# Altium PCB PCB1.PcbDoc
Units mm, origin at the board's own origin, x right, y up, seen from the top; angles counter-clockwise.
Board outline 80 x 70 mm, 2 copper layers (Top Layer, Bottom Layer); 81 components, 50 nets, 233 pads, 0 vias.
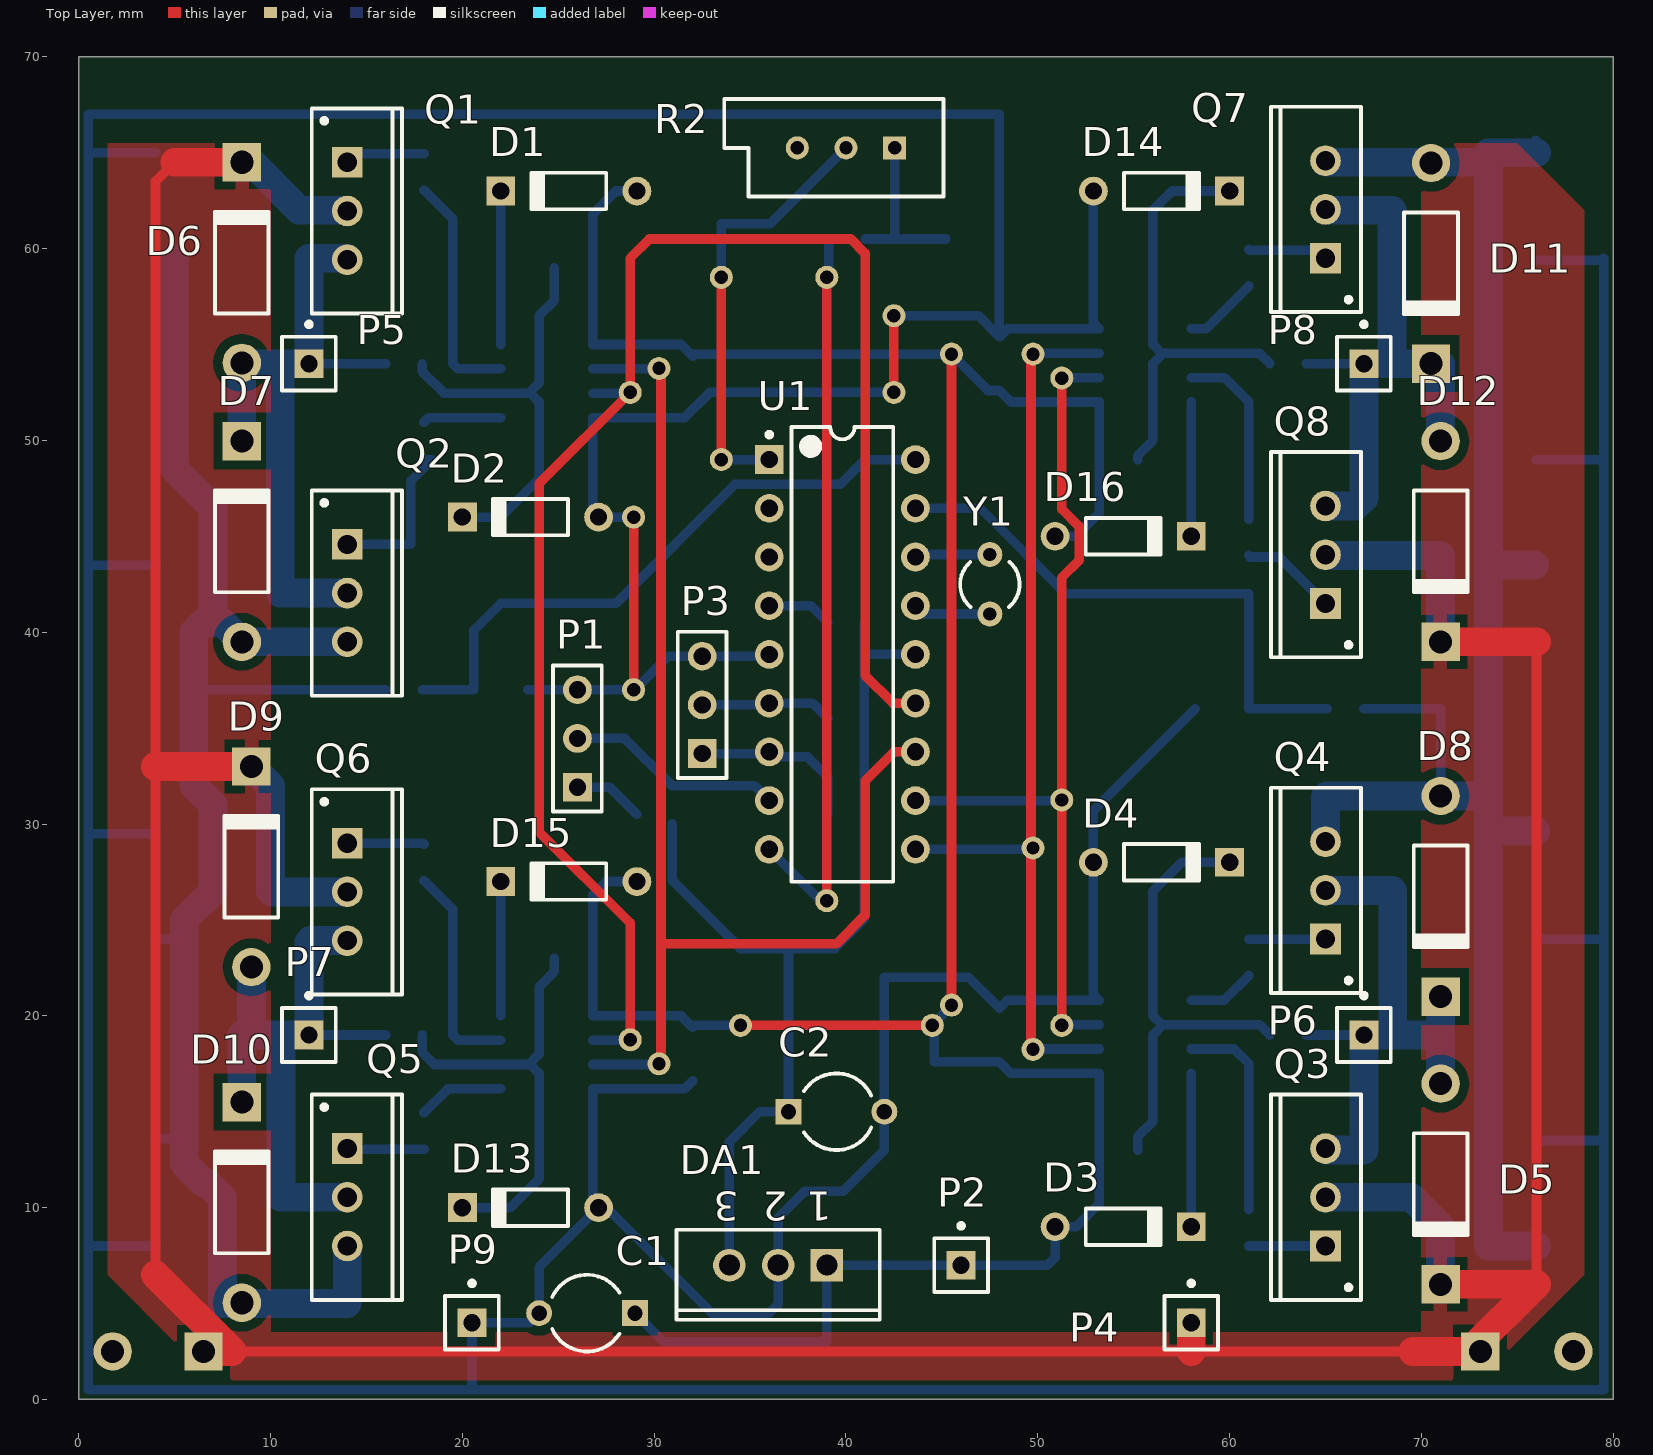
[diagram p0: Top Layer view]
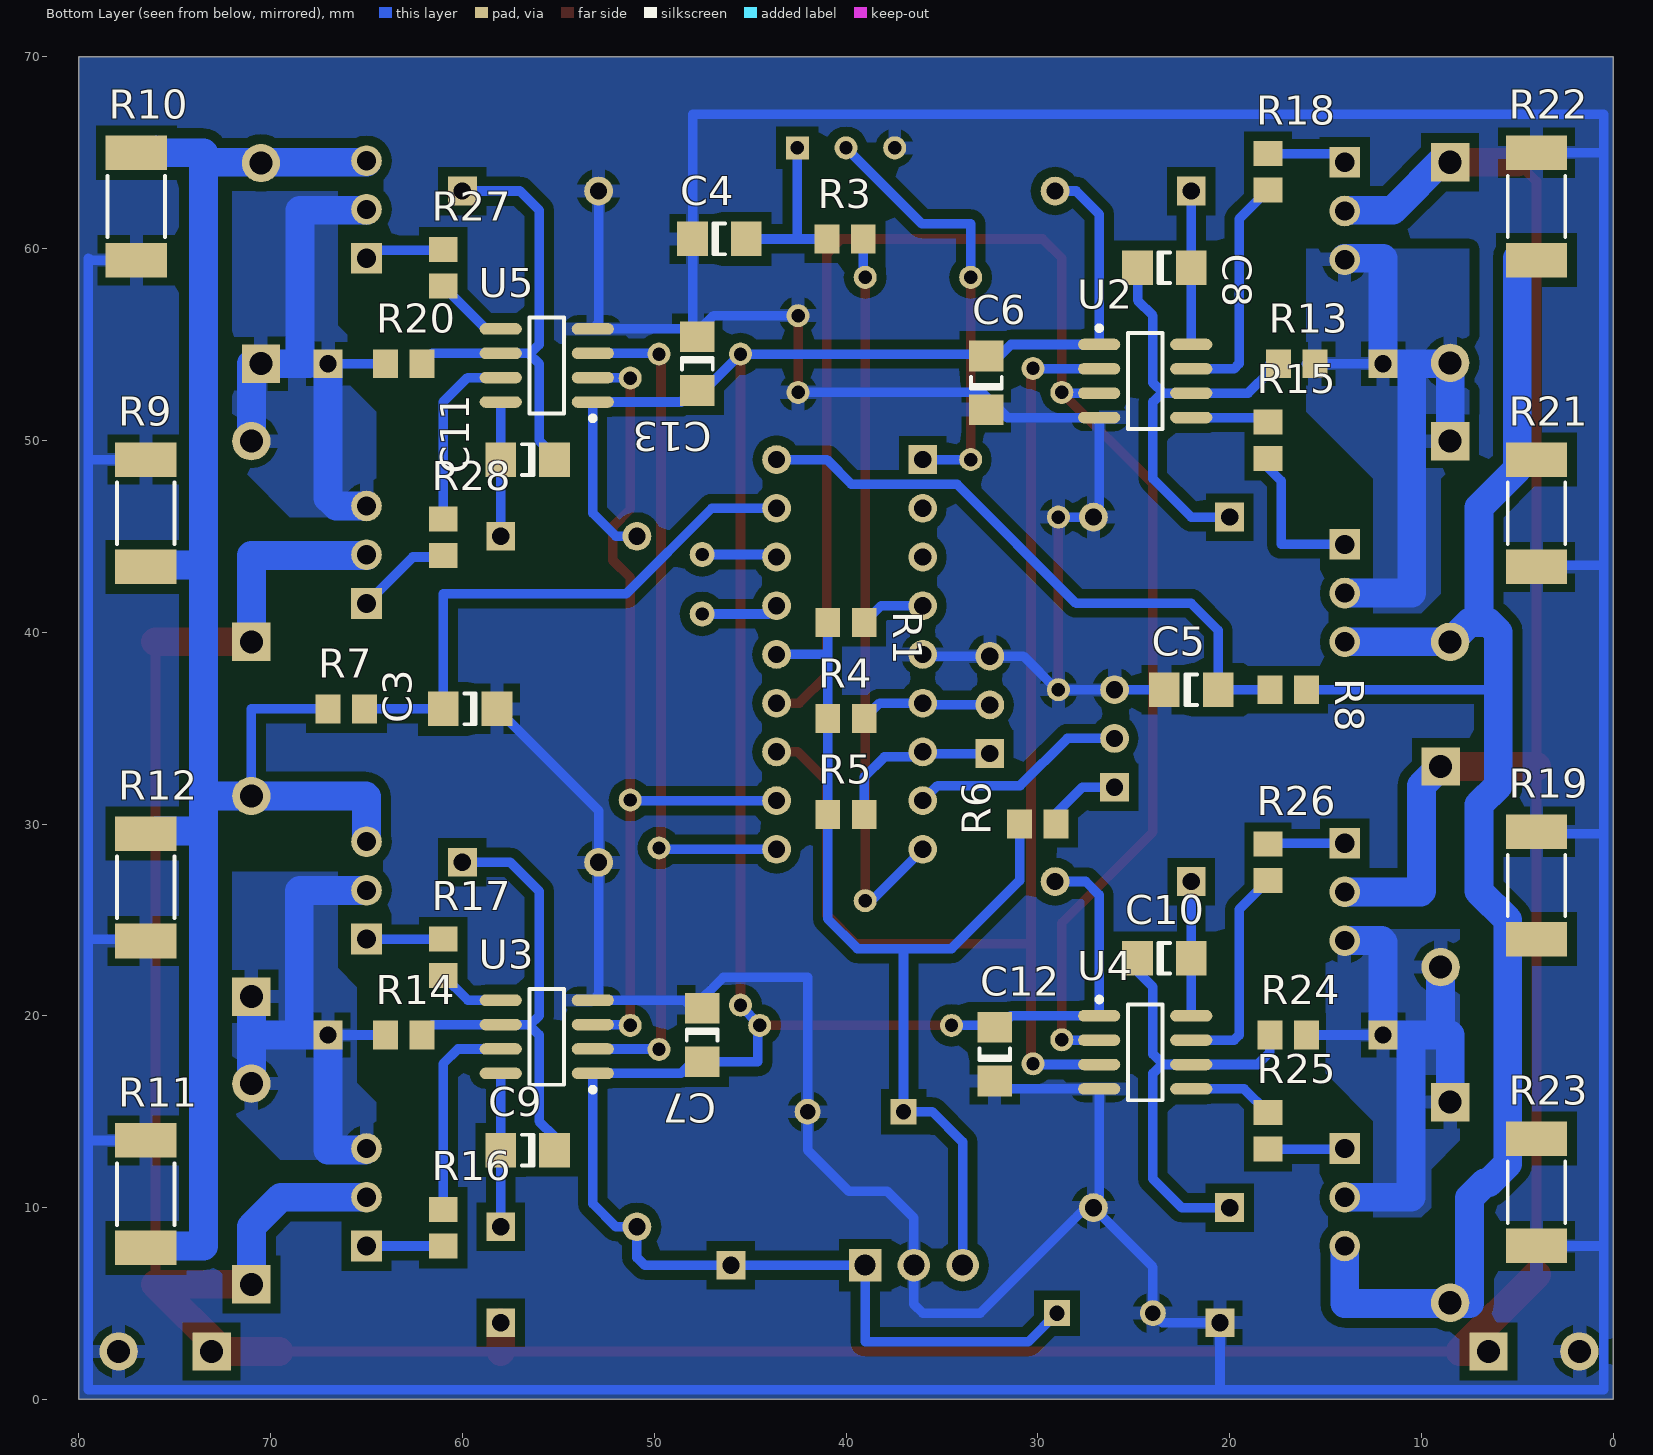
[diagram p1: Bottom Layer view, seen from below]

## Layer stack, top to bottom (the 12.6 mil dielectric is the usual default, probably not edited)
Top Solder: solder mask 0.0102, Solder Resist, Dk 3.5
Top Layer: signal copper 0.0356
Dielectric 1: dielectric 0.32, FR-4, Dk 4.8
Bottom Layer: signal copper 0.0356
Bottom Solder: solder mask 0.0102, Solder Resist, Dk 3.5

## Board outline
0,0 80,0 80,70 0,70

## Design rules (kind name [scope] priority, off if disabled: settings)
Clearance [InPolygon] p1: gap=0.5 ignorepadtopadclearanceinfootprint=FALSE
Clearance Clearance_1 [All] p2: gap=0.254 ignorepadtopadclearanceinfootprint=FALSE except(0: Arc-Hole Track-Hole SMDPad-Hole THPad-Hole Via-Hole Fill-Hole Poly-Hole Region-Hole Text-Hole)
PolygonConnect [All] p1: connectstyle=Relief reliefconductorwidth=0.7 reliefentries=4 polygonreliefangle="90 Angle" airgapwidth=0.4
RoomDefinition Sheet1 [InComponentClass('Sheet1')] p1: confinementstyle=ConfineOut formatcopy=TRUE lockcomponents=FALSE outline -17.25,-31.5 -12,-31.5 -12,-24.75 -17.25,-24.75
RoutingVias [All] p1: holewidth=0.711 width=1.27 viastyle="Through Hole" minholewidth=0.711 minwidth=1.27 maxholewidth=0.711 maxwidth=1.27
SolderMaskExpansion [All] p1: expansion=0.102
Width [All] p1: maxlimit=5 minlimit=0.5 preferedwidth=0.5
30 further rules are at their usual default settings.

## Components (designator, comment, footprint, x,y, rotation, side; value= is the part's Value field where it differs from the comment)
C1 "220x25" CAPR5-4X5 26.5,4.5 r180 top
C2 "10x15" CAPR5-4X5 39.5,15 r0 top
C3 "220pf" 1206 59.6,36 r0 bottom
C4 "100nf" 1206 46.6,60.5 r180 bottom
C5 "220pf" 1206 22,37 r180 bottom
C6 "100nf" 1206 32.682,53 r90 bottom
C7 "100nf" 1206 47.5,19 r270 bottom
C8 "470nf" 1206 23.4,59 r180 bottom
C9 "470nf" 1206 56.6,13 r0 bottom
C10 "470nf" 1206 23.4,23 r180 bottom
C11 "470nf" 1206 56.6,49 r0 bottom
C12 "100nf" 1206 32.247,18 r90 bottom
C13 "100nf" 1206 47.75,54 r270 bottom
D1 "1N4148" DO-35 25.55,63 r180 top
D2 "Diode 1N4148" DO-35 23.55,46 r180 top
D3 "1N4148" DO-35 54.45,9 r0 top
D4 "Diode 1N4148" DO-35 56.45,28 r0 top
D5 "FR307" DO-41 71,11.23 r270 top
D6 "FR307" DO-41 8.5,59.27 r90 top
D7 "FR307" DO-41 8.5,44.73 r90 top
D8 "FR307" DO-41 71,26.23 r270 top
D9 "FR307" DO-41 9,27.77 r90 top
D10 "FR307" DO-41 8.5,10.27 r90 top
D11 "FR307" DO-41 70.5,59.23 r270 top
D12 "FR307" DO-41 71,44.73 r270 top
D13 "Diode 1N4148" DO-35 23.55,10 r180 top
D14 "Diode 1N4148" DO-35 56.45,63 r0 top
D15 "1N4148" DO-35 25.55,27 r180 top
D16 "1N4148" DO-35 54.45,45 r0 top
DA1 "L78M05CV" TO-220A 36.46,7 r180 top
P1 "Header 3" HDR1X3 26,31.92 r90 top
P2 "A" PIN1 46,7 r0 top
P3 "Header 3" HDR1X3 32.5,33.67 r90 top
P4 "A" PIN1 58,4 r0 top
P5 "A" PIN1 12,54 r0 top
P6 "B" PIN1 67,19 r0 top
P7 "C" PIN1 12,19 r0 top
P8 "D" PIN1 67,54 r0 top
P9 "A" PIN1 20.5,4 r0 top
Q1 "IRFZ44" TO-220AB 14,61.96 r270 top
Q2 "IRFZ44" TO-220AB 14,42.04 r270 top
Q3 "IRFZ44" TO-220AB 65,10.54 r90 top
Q4 "IRFZ44" TO-220AB 65,26.54 r90 top
Q5 "IRFZ44" TO-220AB 14,10.54 r270 top
Q6 "IRFZ44" TO-220AB 14,26.46 r270 top
Q7 "IRFZ44" TO-220AB 65,62.04 r90 top
Q8 "IRFZ44" TO-220AB 65,44.04 r90 top
R1 "10k" 6-0805 40,40.5 r180 bottom
R2 "10k" VR5 40,65.25 r180 top value=1K
R3 "10k" 6-0805 40.05,60.5 r180 bottom
R4 "4.7k" 6-0805 40,35.5 r0 bottom
R5 "4.7k" 6-0805 40,30.5 r0 bottom
R6 "4.7k" 6-0805 30,30 r0 bottom
R7 "1k" 6-0805 66.05,36 r0 bottom
R8 "1k" 6-0805 16.95,37 r180 bottom
R9 "1om" 1T-2512 76.5,46.2 r270 bottom
R10 "1om" 1T-2512 77,62.2 r90 bottom
R11 "1om" 1T-2512 76.5,10.7 r270 bottom
R12 "1om" 1T-2512 76.5,26.7 r90 bottom
R13 "10om" 6-0805 16.498,54 r180 bottom
R14 "10om" 6-0805 63.05,19 r0 bottom
R15 "33om" 6-0805 18,50 r270 bottom
R16 "33om" 6-0805 61,8.95 r270 bottom
R17 "33om" 6-0805 61,23.05 r90 bottom
R18 "33om" 6-0805 18,64 r90 bottom
R19 "1om" 1T-2512 4,26.8 r90 bottom
R20 "10om" 6-0805 63.05,54 r180 bottom
R21 "1om" 1T-2512 4,46.2 r270 bottom
R22 "1om" 1T-2512 4,62.2 r90 bottom
R23 "1om" 1T-2512 4,10.8 r270 bottom
R24 "10om" 6-0805 16.95,19 r0 bottom
R25 "33om" 6-0805 18,14 r90 bottom
R26 "33om" 6-0805 18,28 r270 bottom
R27 "33om" 6-0805 61,59 r270 bottom
R28 "33om" 6-0805 61,44.95 r90 bottom
U1 "PIC16F628A-I/P" PDIP300-P18 39.81,38.84 r0 top
U2 "IR2101S" SO-8_N 24.4,53.095 r180 bottom
U3 "IR2101S" SO-8_N 55.6,18.905 r0 bottom
U4 "IR2101S" SO-8_N 24.4,18.095 r180 bottom
U5 "IR2101S" SO-8_N 55.6,53.905 r0 bottom
Y1 "20Mhz" R38 47.5,42.5 r0 top

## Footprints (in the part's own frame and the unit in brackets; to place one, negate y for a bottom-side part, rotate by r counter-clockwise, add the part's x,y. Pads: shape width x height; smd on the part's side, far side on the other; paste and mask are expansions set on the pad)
1T-2512 [mm] "Chip Resistor; Body 6.4 x 3.2 mm (LxW typ)"
  rect 1.8x3.2 smd: 1(-2.8,0) 2(2.8,0)
  silkscreen extent -1.6,-1.5 1.6,1.5
6-0805 [mm] "Chip Resistor; Body 2 x 1.2 mm (LxW typ)"
  rect 1.3x1.5 smd: 1(-0.95,0) 2(0.95,0)
1206 [mm] "Chip Capacitor; Body 3.2 x 1.6 mm (LxW typ)"
  rect 1.6x1.8 smd: 1(-1.4,0) 2(1.4,0)
  silkscreen extent -0.3,-0.8 0.3,0.8
CAPR5-4X5 [mm] "Capacitor; 2 Leads"
  rect 1.35x1.35 hole 0.8: 1(-2.5,0)
  round 1.35 hole 0.8: 2(2.5,0)
  silkscreen extent -1.69,-2 1.82,2
DO-35 [mm] "Diode, Axial; Body 3.8 x 1.9 mm (LxDia. max), Lead Dia. 0.53 mm (max)"
  round 1.5 hole 0.9: 1(-3.55,0)
  rect 1.5x1.5 hole 0.9: 2(3.55,0)
  silkscreen extent -1.95,-0.95 2.05,0.95
DO-41 [mm] "Diode, Axial; Body 5.2 x 2.7 mm (LxDia. max), Lead Dia. 0.86 mm (max)"
  round 2 hole 1.2: 1(-5.23,0)
  rect 2x2 hole 1.2: 2(5.23,0)
  silkscreen extent -2.65,-1.4 2.75,1.4
HDR1X3 [mm] "Connector; Header; 3 Position"
  rect 1.5x1.5 hole 0.9: 1(0,0)
  round 1.5 hole 0.9: 2(2.54,0) 3(5.08,0)
  silkscreen extent -1.27,-1.27 6.35,1.27
PDIP300-P18 [mm] "DIP, 18-Leads, Row Spacing 7.62mm, Pitch 2.54mm, Body 22.9x6.6mm"
  rect 1.5x1.5 hole 0.9: 1(-3.81,10.16)
  round 1.5 hole 0.9: 2(-3.81,7.62) 3(-3.81,5.08) 4(-3.81,2.54) 5(-3.81,0) 6(-3.81,-2.54) 7(-3.81,-5.08) 8(-3.81,-7.62) 9(-3.81,-10.16) 10(3.81,-10.16) 11(3.81,-7.62) 12(3.81,-5.08) 13(3.81,-2.54) 14(3.81,0) 15(3.81,2.54) 16(3.81,5.08) 17(3.81,7.62) 18(3.81,10.16)
  silkscreen extent -3.93,-11.85 2.65,11.85, body extent -3.6,-11.8 3.6,11.8, height 5.34
PIN1 [mm] "Connector; Plug"
  rect 1.5x1.5 hole 0.9: 1(0,0)
  silkscreen extent -1.4,-1.4 1.4,2.17
R38 [mm] "Crystal, Thru-Hole; 2 Leads; Body 3.1 x 8.2 mm (Dia.xH)"
  round 1.3 hole 0.7: 1(0,1.55) 2(0,-1.55)
  silkscreen extent -1.55,-1.19 1.55,1.17
SO-8_N [mm] "SOIC, 8-Leads, Body 4.9x3.9mm, Pitch 1.27mm, IPC Medium Density"
  oval 2.2x0.6 smd: 1(-2.4,1.905) 2(-2.4,0.635) 3(-2.4,-0.635) 4(-2.4,-1.905) 5(2.4,-1.905) 6(2.4,-0.635) 7(2.4,0.635) 8(2.4,1.905)
  silkscreen extent -2.53,-2.5 0.9,2.88, body extent -1.95,-2.45 1.95,2.45, height 1.75
TO-220A [mm] "TO, Thru-Hole, Vertical, Heatsink Mounted; 3 In-Line Leads; Pitch 2.54 mm"
  rect 1.7x1.7 hole 1.1: 1(-2.54,0)
  round 1.7 hole 1.1: 2(0,0) 3(2.54,0)
  silkscreen extent -5.3,-1.85 5.3,2.85
TO-220AB [mm] "TO, Thru-Hole, Vertical, Heatsink Mounted; 3 In-Line Leads; Pitch 2.54 mm"
  rect 1.6x1.6 hole 1: 1(-2.54,0)
  round 1.6 hole 1: 2(0,0) 3(2.54,0)
  silkscreen extent -5.35,-1.85 5.35,2.85, body extent -5.4,-1.9 5.4,2.9, height 19.3
VR5 [mm] "Thru-Hole; 3 Leads"
  rect 1.2x1.2 hole 0.7: 1(-2.54,0)
  round 1.2 hole 0.7: 2(0,0) 3(2.54,0)
  silkscreen extent -5.08,-2.54 6.35,2.54

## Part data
C1 C2: library part Cap2, "Capacitor"
C3 C4 C5 C6 C7 C8 C9 C10 C11 C12 C13: library part C1206, "Ceramic Chip Capacitor - Standard", PackageDocument=Mar-2001
D1 D3 D15 D16: library part "Diode 1N4148", "High Conductance Fast Diode"
D2 D4 D13 D14: "High Conductance Fast Diode"
D5 D6 D7 D8 D9 D10 D11 D12: library part "Diode 1N4007", "1 Amp General Purpose Rectifier"
DA1: Manufacturer=STMicroelectronics, Package="TO-220 L", ValueBOM="5В 500мА"
P1 P3: "Header, 3-Pin"
P2 P4 P5 P6 P7 P8 P9: library part Plug, "Plug"
Q1 Q2 Q3 Q4 Q5 Q6 Q7 Q8: "HEXFET N-Channel Power MOSFET"
R1 R3 R4 R5 R6 R7 R8 R13 R14 R15 R16 R17 R18 R20 R24 R25 R26 R27 R28: library part ERJ6RB, "Precision Thick Film Chip Resistor, 10 Ohm to 1M Ohm Range, 1% and 0.5% Tolerance, 0805 Size, 0.1 W", PackageDocument=Mar-2003
R2: library part RPot, "Potentiometer"
R9 R10 R11 R12 R19 R21 R22 R23: library part ERJ1TRS, "Low Ohmic Value Thick Film Chip Resistor, 0.1 Ohm to 0.2 Ohm Range, 1%, 2% and 5% Tolerance, 2512 Size, 1 W", PackageDocument=Mar-2003
U1: "FLASH-Based 8-Bit CMOS Microcontroller with nanoWatt Technology, 2K (x14-Bit words) FLASH, 224 Bytes SRAM, 18-Pin PDIP, 3.0 to 5.5V Supply Range, Industrial Temperature", Supplier Part Number 1=PIC16F628A-I/P-ND
U2 U3 U4 U5: "High and Low Side Driver"
Y1: library part XTAL, "Crystal Oscillator"

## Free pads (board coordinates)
  round 1.2 hole 0.7: 36(39,58.5) 37(39,26) 38(34.5,19.5) 39(44.5,19.5) 40(45.5,54.5) 42(45.5,20.558) 43(33.5,49) 44(33.5,58.5) 45(42.5,56.5) 46(42.5,52.5) 47(28.927,46) 48(28.927,37) 49(30.25,53.75) 50(28.75,52.5) 51(28.75,18.75) 52(30.25,17.5) 53(49.75,18.25) 54(51.25,19.5) 55(51.25,53.25) 56(49.75,54.5) 57(51.25,31.25) 58(49.75,28.75)
  round 2 hole 1.2: 59(1.768,2.5) 61(77.921,2.5)
  rect 2x2 hole 1.2: 60(6.5,2.5) 62(73.07,2.5)

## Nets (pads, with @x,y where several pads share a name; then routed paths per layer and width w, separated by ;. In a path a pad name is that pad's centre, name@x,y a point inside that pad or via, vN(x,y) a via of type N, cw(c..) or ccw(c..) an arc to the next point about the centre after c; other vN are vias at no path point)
5V: C2.1 DA1.3 R1.1 R4.2 R5.2 R6.2 U1.14 | length 51.9
  Bottom Layer w0.5: R6.2 30.95,27.05 34.5,23.5 37,23.5 ; DA1.3 33.92,13.42 35.5,15 C2.1 37,23.5 ; R1.1 40.95,39 ; U1.14 41.11,38.84 40.95,39 ; 37,23.5 39.4,23.5 40.95,25.05 R5.2 40.95,39
12V: C1.1 C6.2 C7.2 C12.2 C13.2 D1.1 D3.1 D15.1 D16.1 DA1.1 P2.1 pad.38 pad.39 pad.40 pad.42 U2.1 U3.1 U4.1 U5.1 | length 156.9
  Top Layer w0.5: pad.38 pad.39 ; pad.42 pad.40
  Bottom Layer w0.5: C1.1 30.5,3 39,3 DA1.1 P2.1 50.5,7 50.9,7.4 D3.1 52,9 53.2,10.2 U3.1 48.6,17 48,17.6 C7.2 44.6,17.6 44.6,19.4 pad.39 pad.42 ; D15.1 27.5,27 26.8,26.3 U4.1 31.4,20 32,19.4 32.1,19.5 pad.38 ; D1.1 28,63 26.8,61.8 U2.1 31.4,55 32,54.4 32.1,54.5 pad.40 47.4,52.6 C13.2 48,52.6 48.6,52 U5.1 53.2,46.2 52,45 D16.1
GND: C1.2 C2.2 C3.1 C4.1 C5.1 C6.1 C7.1 C12.1 C13.1 D2.1 D4.1 D13.1 D14.1 DA1.2 P1.3 P3.3 P9.1 pad.45 pad.46 pad.47 pad.48 pad.59 pad.61 R2.3 R9.1 R10.1 R11.1 R12.1 R19.2 R21.2 R22.2 R23.2 U1.5 U2.4 U3.4 U4.4 U5.4 | length 447.7
  Top Layer w0.5: pad.48 pad.47 ; pad.46 pad.45
  Bottom Layer w0.5: R23.2 0.5,8 ; R19.2 3.9,29.5 0.5,29.5 ; R21.2 3.9,43.5 0.5,43.5 ; R22.2 0.5,65 ; C5.1 P1.3 29,37 30.75,38.75 P3.3 35.91,38.75 U1.5 ; pad.47 D2.1 26.8,46.3 U2.4 31.59,51.19 32.9,52.5 pad.46 ; C12.1@32,16.6 31.59,16.19 U4.4 26.8,10.3 D13.1 ; pad.45 46.9,56.5 C13.1@48,55.4 ; D14.1 52.9,56.11 U5.4 48.41,55.81 C13.1@48,55.4 ; C3.1 52.9,30.7 D4.1 52.9,21.11 U3.4 48.41,20.81 48,20.4 46.4,22 42,22 C2.2 42,13 39.845,10.845 37.845,10.845 36.46,9.46 DA1.2 36.46,4.96 36,4.5 33,4.5 27.5,10 D13.1 ; R11.1@76,13.6 76.1,13.5 R11.1 79.5,13.5 ; R12.1@76,24 79.5,24 ; R9.1@76,49 R9.1 79.5,49 ; R10.1@76,59.4 79.4,59.4 79.5,59.5 79.5,49 ; 0.5,8 0.5,29.5 ; 0.5,8 0.5,0.5 20.5,0.5 ; 0.5,29.5 0.5,43.5 ; 0.5,43.5 0.5,65 ; 0.5,65 0.5,67 48,67 C4.1 C13.1@48,55.4 ; 20.5,0.5 P9.1 23.5,4 C1.2 24,6.9 D13.1 ; 20.5,0.5 79.5,0.5 79.5,13.5 ; 79.5,13.5 79.5,24 ; 79.5,24 79.5,49
NetC3_2: C3.2 R7.1 U1.17 | length 29.3
  Bottom Layer w0.5: U1.17 47,46.46 51.46,42 61,42 C3.2 R7.1
NetC4_2: C4.2 R2.1 R3.1 | length 9
  Bottom Layer w0.5: R3.1 42.5,60.5 ; R2.1 42.54,60.54 42.5,60.5 ; C4.2 42.5,60.5
NetC5_2: C5.2 R8.1 U1.18 | length 32.5
  Bottom Layer w0.5: R8.1 C5.2 20.6,40.1 22,41.5 28,41.5 34.214,47.714 39.714,47.714 41,49 U1.18
NetC8_1: C8.1 D2.2 R13.1 U2.6 | length 23.1
  Bottom Layer w0.5: R13.1@17.9,54 17.9,53.6 19.04,52.46 U2.6 23.46,52.46 ; D2.2 22,46 24,48 24,52 23.54,52.46 23.46,52.46 ; C8.1 24.8,57.3 24,56.5 24,53 23.46,52.46
NetC8_2: C8.2 D1.2 U2.8 | length 8
  Bottom Layer w0.5: U2.8 C8.2 D1.2
NetC9_1: C9.1 D4.2 R14.1 U3.6 | length 24.7
  Bottom Layer w0.5: C9.1 55.2,13.7 56,14.5 56,19 56.54,19.54 ; D4.2 57.5,28 56,26.5 56,20 56.46,19.54 56.54,19.54 ; R14.1 61.56,19.54 U3.6 56.54,19.54
NetC9_2: C9.2 D3.2 U3.8 | length 8
  Bottom Layer w0.5: D3.2 C9.2 U3.8
NetC10_1: C10.1 D13.2 R24.2 U4.6 | length 23.7
  Bottom Layer w0.5: R24.2 17.9,18.1 18.54,17.46 U4.6 23.46,17.46 ; D13.2 22.5,10 24,11.5 24,17 23.54,17.46 23.46,17.46 ; C10.1 24.8,22.3 24,21.5 24,18 23.46,17.46
NetC10_2: C10.2 D15.2 U4.8 | length 7
  Bottom Layer w0.5: U4.8 C10.2 D15.2
NetC11_1: C11.1 D14.2 R20.2 U5.6 | length 24
  Bottom Layer w0.5: C11.1 55.2,49.2 56,50 56,54 56.54,54.54 ; D14.2 57,63 56,62 56,55 56.46,54.54 56.54,54.54 ; R20.2 61.56,54.54 U5.6 56.54,54.54
NetC11_2: C11.2 D16.2 U5.8 | length 7
  Bottom Layer w0.5: D16.2 C11.2 U5.8
NetD5_1: D5.1 D8.2 P6.1 Q3.3 Q4.2 R14.2 | length 30.6
  Bottom Layer w0.5: R14.2 P6.1 ; Q3.3 Q3.3@65.08,13 ; 68.46,26.54 68.5,26.5
  Bottom Layer w1.5: Q4.2 68.46,26.54 ; Q3.3@65.08,13 67,13 P6.1 68.5,19 ; 68.5,26.5 68.5,19 ; D5.1 71,19 ; D8.2 71,19 ; 68.5,19 71,19
NetD6_1: D6.1 D7.2 P5.1 Q1.3 Q2.2 R13.2 | length 34.5
  Bottom Layer w0.5: P5.1 R13.2 R13.2@16,54
  Bottom Layer w1.5: D7.2@8.5,50 D6.1 ; D6.1@8.522,54 10.5,54 ; Q2.2 10.5,42.04 10.5,54 ; Q1.3@14,59.5 12,59.5 P5.1 10.5,54
NetD7_1: D7.1 D10.1 Q2.3 Q5.3 R8.2 R19.1 R21.1 R22.1 R23.1 | length 88.5
  Bottom Layer w0.5: R23.1 R23.1@5.5,13.6 ; R19.1 R19.1@5.5,24 ; R22.1 4.1,59.5 R22.1@5,59.5 ; 6,37 R8.2
  Bottom Layer w1.5: R22.1@5,59.5 5,48.5 7,46.5 7,41 ; Q5.3 14,5 7.5,5 7.5,10.5 6.703,11.297 6.496,11.297 5.5,12.293 5.5,13.6 5.5,24 5.5,25 7,26.5 7,31 6,32 6,37 6,40 6.5,40.5 7.5,40.5 D7.1 Q2.3
NetD8_1: D8.1 D11.1 Q4.3 Q7.3 R7.2 R9.2 R10.2 R11.2 R12.2 | length 98.1
  Bottom Layer w0.5: 65,31.42 65.04,31.46 ; R7.2 71,36 D8.1 ; 73.5,29.6 76,29.6 R12.2@75.96,29.64 ; R9.2@75.9,43.5 R9.2@76,43.4 ; R10.2@75.96,65.645 75.96,65.04 R10.2@76,65
  Bottom Layer w1.5: Q4.3 65,31.42 ; Q7.3@65,64.5 73.5,64.5 ; 65.04,31.46 D8.1 73.5,31.46 ; 73.5,29.6 73.5,8 R11.2@76,8 ; R9.2@75.9,43.5 73.5,43.5 ; R12.2@75.96,29.64 73.5,29.64 73.5,31.46 ; R10.2@76,65 73.5,65 73.5,64.5 ; 73.5,31.46 73.5,43.5 ; 73.5,43.5 73.5,64.5
NetD9_1: D9.1 D10.2 P7.1 Q5.2 Q6.3 R24.1 | length 33.8
  Bottom Layer w0.5: D10.2@8,15.46 D10.2@8.5,15.96 ; 8.5,19 9,19.5 ; 10.5,19 10.54,18.96 ; P7.1 R24.1 ; 12,23.84 12.08,23.92
  Bottom Layer w1.5: D10.2@8.5,15.96 8.5,19 10.5,19 P7.1 12,23.84 ; 9,19.5 D9.1 ; 10.54,18.96 10.54,10.54 Q5.2 ; 12.08,23.92 Q6.3
NetD11_2: D11.2 D12.1 P8.1 Q7.2 Q8.3 R20.1 | length 31.9
  Bottom Layer w0.5: R20.1 P8.1 68,54 68.46,54.46
  Bottom Layer w1.5: Q8.3 66.58,46.58 67,47 P8.1 ; Q7.2@65,62 68.46,62 68.46,54.46 ; 68,54 D11.2 71,54 D12.1
NetP1_1: P1.1 R6.1 | length 3.7
  Bottom Layer w0.5: P1.1 27.68,31.92 R6.1@29.1,30.5
NetP1_2: P1.2 U1.8 | length 11.3
  Bottom Layer w0.5: P1.2 28.46,34.46 30.92,32 35.22,32 U1.8
NetP3_1: P3.1 R5.1 U1.7 | length 9.1
  Bottom Layer w0.5: P3.1 35.91,33.67 U1.7 36.26,33.5 38,33.5 39.05,32.45 R5.1
NetP3_2: P3.2 R4.1 U1.6 | length 6.9
  Bottom Layer w0.5: P3.2 35.91,36.21 U1.6 38.25,36.3 R4.1
NetQ1_1: Q1.1 R18.2 | length 4
  Bottom Layer w0.5: Q1.1@14,65 14.05,64.95 R18.2
NetQ2_1: Q2.1 R15.2 | length 8.7
  Bottom Layer w0.5: Q2.1 17.315,44.58 17.315,47.895 18.235,48.815 18.42,49 17.95,49 R15.2
NetQ3_1: Q3.1 R16.2 | length 4
  Bottom Layer w0.5: R16.2 Q3.1
NetQ4_1: Q4.1 R17.2 | length 4
  Bottom Layer w0.5: R17.2 Q4.1
NetQ5_1: Q5.1 R25.1 | length 4
  Bottom Layer w0.5: Q5.1 14.03,13.05 R25.1
NetQ6_1: Q6.1 R26.1 | length 4
  Bottom Layer w0.5: Q6.1 17.95,29 R26.1
NetQ7_1: Q7.1 R27.1 | length 4
  Bottom Layer w0.5: R27.1 61.03,59.92 Q7.1@65,59.92
NetQ8_1: Q8.1 R28.1 | length 5
  Bottom Layer w0.5: R28.1 61.08,43.92 62.58,43.92 Q8.1
NetR1_2: R1.2 U1.4 | length 3.4
  Bottom Layer w0.5: U1.4 38.17,41.38 R1.2
NetR2_3: pad.43 pad.44 R2.2 U1.1 | length 22.9
  Top Layer w0.5: pad.43 pad.44
  Bottom Layer w0.5: pad.43@33.5,49 U1.1 ; pad.44 33.5,61.29 36.04,61.29 R2.2
NetR3_2: pad.36 pad.37 R3.2 U1.9 | length 38.7
  Top Layer w0.5: pad.37 pad.36
  Bottom Layer w0.5: U1.9 38.68,26 pad.37 ; pad.36 39.1,58.6 R3.2
NetR15_1: R15.1 U2.5 | length 4.1
  Bottom Layer w0.5: R15.1 18.24,51.19 U2.5
NetR16_1: R16.1 U3.7 | length 10.9
  Bottom Layer w0.5: U3.7 60.23,18.27 61,17.5 R16.1
NetR17_1: R17.1 U3.5 | length 3.5
  Bottom Layer w0.5: U3.5 59.71,20.81 R17.1
NetR18_1: R18.1 U2.7 | length 12.3
  Bottom Layer w0.5: R18.1 19.5,61.55 19.5,54 19.77,53.73 U2.7
NetR25_2: R25.2 U4.5 | length 4.5
  Bottom Layer w0.5: R25.2 19.24,16.19 U4.5
NetR26_2: R26.2 U4.7 | length 11.3
  Bottom Layer w0.5: R26.2 19.5,25.55 19.5,19 19.77,18.73 U4.7
NetR27_2: R27.2 U5.5 | length 3.9
  Bottom Layer w0.5: U5.5 58.76,55.81 R27.2
NetR28_2: R28.2 U5.7 | length 9.6
  Bottom Layer w0.5: U5.7 59.73,53.27 61,52 R28.2
NetU1_10: pad.53 pad.56 pad.58 U1.10 U3.2 U5.3 | length 49.5
  Top Layer w0.5: pad.53 49.646,18.354 49.646,54.5 pad.56
  Bottom Layer w0.5: U1.10 49.68,28.68 pad.58 ; pad.53 49.77,18.27 U3.2 ; pad.56 49.79,54.54 U5.3
NetU1_11: pad.54 pad.55 pad.57 U1.11 U3.3 U5.2 | length 46.1
  Top Layer w0.5: pad.54 pad.57 51.25,42.842 52.154,43.746 52.154,45.519 51.25,46.423 pad.55
  Bottom Layer w0.5: U1.11 51.22,31.22 pad.57 ; pad.54 51.29,19.54 U3.3 ; pad.55 51.27,53.27 U5.2
NetU1_12: pad.49 pad.52 U1.12 U2.2 U4.3 | length 64.8
  Top Layer w0.5: pad.52 30.354,17.604 30.354,23.75 ; pad.49 30.354,53.75 30.354,23.75 ; U1.12 42.51,33.76 41,32.25 41,25.25 39.5,23.75 30.354,23.75
  Bottom Layer w0.5: U4.3 30.21,17.46 pad.52 ; U2.2 30.23,53.73 pad.49
NetU1_13: pad.50 pad.51 U1.13 U2.3 U4.2 | length 86.8
  Top Layer w0.5: pad.51 28.75,24.842 24,29.592 24,47.75 pad.50 28.75,59.5 29.75,60.5 40.25,60.5 41,59.75 41,37.75 42.45,36.3 U1.13
  Bottom Layer w0.5: U4.2 28.73,18.73 pad.51 ; U2.3 28.71,52.46 pad.50
NetU1_15: U1.15 Y1.2 | length 4.1
  Bottom Layer w0.5: U1.15 44.05,40.95 Y1.2
NetU1_16: U1.16 Y1.1 | length 3.9
  Bottom Layer w0.5: U1.16 43.75,44.05 Y1.1
VCC: D5.2 D6.2 D9.2 D12.2 P4.1 pad.60 pad.62 Q1.2 Q3.2 Q6.2 Q8.2 | length 226.5
  Top Layer w0.5: 4,6.5 4,33 4,63.5 5,64.5 ; 8,2.5 58,2.5 69.547,2.5 ; pad.62@72.5,2.5 pad.62 ; 76,6 76,39.5
  Top Layer w1.5: 4,6.5 8,2.5 pad.60 ; 4,33 D9.2 ; 5,64.5 D6.2 ; 58,2.5 P4.1 ; 69.547,2.5 72.5,2.5 76,6 D5.2 ; D12.2 73.625,39.5 74.875,39.5 76,39.5
  Bottom Layer w1.5: D6.2@8.75,64.75 11.5,62 Q1.2@14,62 ; D9.2 10,32 10,26.5 10.04,26.46 Q6.2 ; Q3.2 69.46,10.54 71,9 D5.2 ; Q8.2@65,44 71,44 D12.2
pads on no net: U1.2 U1.3

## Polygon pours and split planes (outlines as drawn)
GND on Bottom Layer "Top L1-No Net" (solid, remove dead copper, pour order 22): 0,70 80,70 80,0 0,0
NetD11_2 on Bottom Layer "Top L1-No Net" (solid, pour order 20): 66.5,63 72,63 72,49 69,46 64.5,46 64.5,51.5 66,53 66,55.5 66.5,56
NetD5_1 on Bottom Layer "Top L1-No Net" (solid, pour order 18): 66.5,27.5 72,27.5 72,15 69.5,12.5 64.5,12.5 64.5,15.5 65.5,16.5 65.5,21.5 66.5,22.5
NetD9_1 on Bottom Layer "Top L1-No Net" (solid, pour order 14): 8,24.5 15,24.5 15,17 12.5,14.5 12.5,9.5 10,9.5 9.5,10 9.5,12 8,13.5
NetD6_1 on Bottom Layer "Top L1-No Net" (solid, pour order 12): 7.5,60 16,60 16,51.5 12.5,48 12.5,41 10,41 9,42 9,48 7.5,49.5
VCC on Top Layer "Top L1-No Net" (solid, pour order 24): 10,65.5 10,3.5 70,3.5 70,65.5 75,65.5 78.5,62 78.5,6.5 73,1 7,1 1.5,6.5 1.5,65.5

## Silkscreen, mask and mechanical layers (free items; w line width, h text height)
Mechanical 1:
  the board outline again, w0.254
